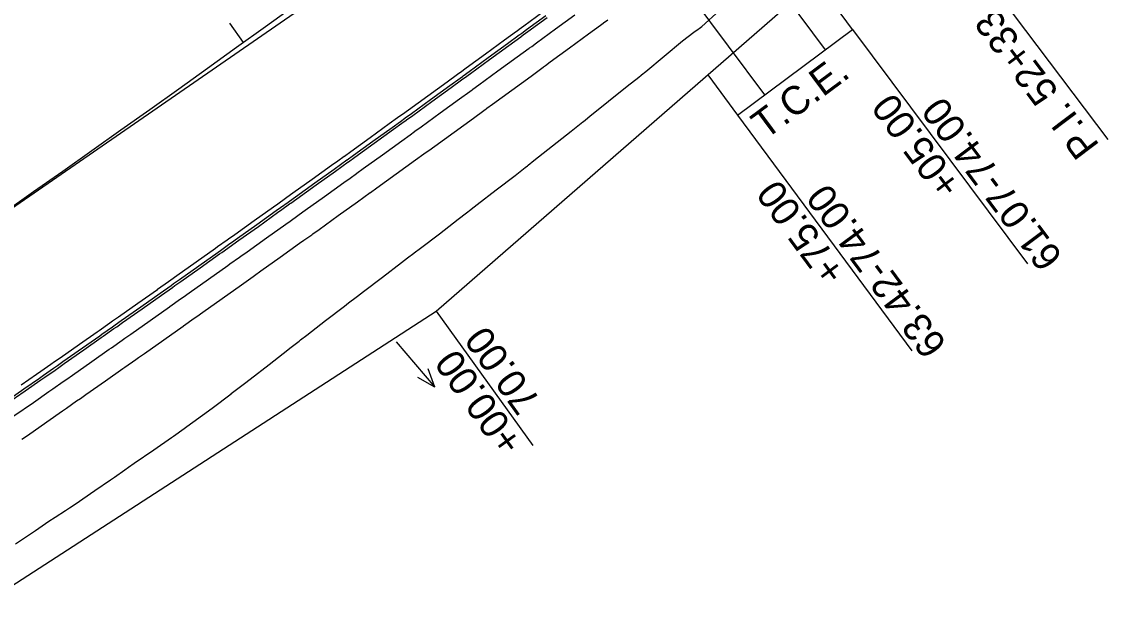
# Model space of a CAD drawing. Extents: x 1147550 to 1149124, y 2017436 to 2018779.
# Drawn here: x 1148333.9 to 1148565.1, y 2017968.7 to 2018092.6 of the extents above; entities that cross this region are included whole.
import ezdxf

# ---------------------------------------------------------------- set-up
doc = ezdxf.new("R2010")
doc.units = 0
for name, color, linetype in [('S_EDGE_CONCRETE', 7, 'Continuous'), ('S_ELECTRIC_UTILITIES', 7, 'Continuous'), ('S_HEADWALL', 7, 'Continuous'), ('S_IRON_PIN', 7, 'Continuous'), ('S_MAILBOX', 7, 'Continuous'), ('S_RDW_PT_SYM', 7, 'Continuous'), ('S_SECONDARY_CTL', 7, 'Continuous'), ('S_TANK', 7, 'Continuous'), ('S_TELEPHONE_UTILITIES', 7, 'Continuous')]:
    doc.layers.add(name, color=color, linetype=linetype)

msp = doc.modelspace()

# ---------------------------------------------------------------- linework, layer by layer
at = {"layer": 'S_EDGE_CONCRETE'}
msp.add_line((1148293.22, 2018026.54), (1148491.47, 2018163.46), dxfattribs=at)
msp.add_lwpolyline([(1148377.87, 2018092.3), (1148380.78, 2018088.23)], dxfattribs=at)
msp.add_arc((1145037.29, 2022741.09), 5729.58, 304.629463, 309.445337, dxfattribs=at)
at = {"layer": 'S_ELECTRIC_UTILITIES'}
for points in [[(1148509.76, 2018090.99), (1148546.79, 2018041.41)], [(1148485.37, 2018072.88), (1148522.25, 2018022.95)], [(1148421.63, 2018031.39), (1148442.06, 2018002.97)]]:
    msp.add_lwpolyline(points, dxfattribs=at)
at = {"layer": 'S_HEADWALL'}
for p, q in [((1148503.99, 2018086.7), (1148484.62, 2018112.78)), ((1148491.14, 2018077.16), (1148471.77, 2018103.24))]:
    msp.add_line(p, q, dxfattribs=at)
at = {"layer": 'S_IRON_PIN'}
for p, q in [((1148509.76, 2018090.99), (1148502.03, 2018101.35)), ((1148485.37, 2018072.88), (1148509.76, 2018090.99)), ((1148479.08, 2018081.39), (1148485.37, 2018072.88))]:
    msp.add_line(p, q, dxfattribs=at)
at = {"layer": 'S_MAILBOX'}
msp.add_lwpolyline([(1147623.68, 2017436.42), (1147751.67, 2017548.43), (1147958.55, 2017704.02), (1148020.45, 2017753.36), (1148124.6, 2017828.73), (1148174.25, 2017853.51), (1148282.74, 2017941.53), (1148421.63, 2018031.39), (1148612.18, 2018197.22), (1148639.91, 2018214.06), (1148753.45, 2018306.48), (1148799.03, 2018350.69)], dxfattribs=at)
at = {"layer": 'S_RDW_PT_SYM'}
msp.add_lwpolyline([(1148491.47, 2018163.46), (1148563.75, 2018067.67)], dxfattribs=at)
at = {"layer": 'S_SECONDARY_CTL'}
msp.add_lwpolyline([(1148332.6, 2017982.17), (1148336.8, 2017984.98), (1148339.66, 2017986.92), (1148340.99, 2017987.8), (1148343.17, 2017989.22), (1148344, 2017989.76), (1148345.22, 2017990.56), (1148349.41, 2017993.39), (1148352.7, 2017995.66), (1148353.56, 2017996.27), (1148355.73, 2017997.79), (1148356.51, 2017998.35), (1148357.69, 2017999.18), (1148361.84, 2018002.06), (1148365.59, 2018004.62), (1148366.01, 2018004.91), (1148368.31, 2018006.53), (1148368.88, 2018006.94), (1148370.12, 2018007.85), (1148374.19, 2018010.85), (1148378.21, 2018013.91), (1148378.23, 2018013.92), (1148380.5, 2018015.66), (1148381.02, 2018016.05), (1148382.23, 2018016.98), (1148386.24, 2018020.05), (1148390.23, 2018023.16), (1148390.67, 2018023.51), (1148392.64, 2018025.05), (1148392.93, 2018025.27), (1148394.21, 2018026.27), (1148398.19, 2018029.4), (1148402.2, 2018032.46), (1148403.09, 2018033.13), (1148404.71, 2018034.35), (1148404.96, 2018034.53), (1148406.24, 2018035.51), (1148410.25, 2018038.57), (1148414.26, 2018041.65), (1148415.56, 2018042.66), (1148416.89, 2018043.67), (1148416.93, 2018043.7), (1148418.28, 2018044.7), (1148422.31, 2018047.75), (1148426.3, 2018050.85), (1148428.03, 2018052.19), (1148428.92, 2018052.9), (1148429.02, 2018052.97), (1148430.29, 2018053.95), (1148434.3, 2018057.02), (1148438.3, 2018060.11), (1148440.45, 2018061.79), (1148440.94, 2018062.16), (1148441.08, 2018062.28), (1148442.29, 2018063.22), (1148446.26, 2018066.33), (1148450.22, 2018069.47), (1148452.67, 2018071.42), (1148452.78, 2018071.51), (1148453.21, 2018071.85), (1148454.17, 2018072.62), (1148458.11, 2018075.8), (1148462.03, 2018078.99), (1148464.49, 2018080.92), (1148465.02, 2018081.34), (1148465.08, 2018081.39), (1148466, 2018082.11), (1148469.9, 2018085.33), (1148473.78, 2018088.57), (1148476.12, 2018090.42), (1148477.04, 2018091.04), (1148477.25, 2018091.19), (1148477.83, 2018091.58), (1148481.57, 2018095.01)], dxfattribs=at)
at = {"layer": 'S_TANK'}
for p, q in [((1148413.18, 2018024.88), (1148421.33, 2018015.31)), ((1148421.33, 2018015.31), (1148419.9, 2018019.15)), ((1148421.33, 2018015.31), (1148417.77, 2018017.33))]:
    msp.add_line(p, q, dxfattribs=at)
at = {"layer": 'S_TELEPHONE_UTILITIES'}
for points in [[(1148333.8, 2018015.76), (1148337.06, 2018018.04), (1148337.93, 2018018.64), (1148340.09, 2018020.15), (1148340.87, 2018020.7), (1148342.05, 2018021.52), (1148346.16, 2018024.41), (1148349.86, 2018027), (1148350.28, 2018027.3), (1148352.56, 2018028.9), (1148353.14, 2018029.31), (1148354.39, 2018030.19), (1148358.5, 2018033.09), (1148362.61, 2018035.99), (1148362.63, 2018036), (1148364.95, 2018037.64), (1148365.48, 2018038.01), (1148366.71, 2018038.89), (1148370.81, 2018041.8), (1148374.91, 2018044.71), (1148375.37, 2018045.03), (1148377.4, 2018046.47), (1148377.69, 2018046.69), (1148379.01, 2018047.62), (1148383.11, 2018050.54), (1148387.2, 2018053.46), (1148388.09, 2018054.1), (1148389.74, 2018055.28), (1148389.99, 2018055.46), (1148391.29, 2018056.39), (1148395.37, 2018059.32), (1148399.46, 2018062.25), (1148400.79, 2018063.2), (1148402.14, 2018064.17), (1148402.18, 2018064.2), (1148403.54, 2018065.18), (1148407.62, 2018068.12), (1148411.7, 2018071.07), (1148413.46, 2018072.34), (1148414.38, 2018073), (1148414.48, 2018073.08), (1148415.77, 2018074.01), (1148419.84, 2018076.96), (1148423.91, 2018079.92), (1148426.11, 2018081.51), (1148426.6, 2018081.87), (1148426.75, 2018081.98), (1148427.98, 2018082.87), (1148432.04, 2018085.83), (1148436.1, 2018088.8), (1148438.62, 2018090.64), (1148438.73, 2018090.72), (1148439.17, 2018091.04), (1148440.16, 2018091.77), (1148444.22, 2018094.74)], [(1148330.25, 2018012.07), (1148334.38, 2018014.94), (1148337.64, 2018017.22), (1148338.5, 2018017.82), (1148340.66, 2018019.33), (1148341.44, 2018019.88), (1148342.62, 2018020.7), (1148346.74, 2018023.59), (1148350.43, 2018026.18), (1148350.85, 2018026.48), (1148353.14, 2018028.09), (1148353.71, 2018028.49), (1148354.97, 2018029.37), (1148359.08, 2018032.27), (1148363.18, 2018035.17), (1148363.2, 2018035.18), (1148365.52, 2018036.82), (1148366.05, 2018037.2), (1148367.29, 2018038.07), (1148371.39, 2018040.98), (1148375.49, 2018043.89), (1148375.95, 2018044.22), (1148377.98, 2018045.66), (1148378.27, 2018045.87), (1148379.59, 2018046.81), (1148383.69, 2018049.73), (1148387.78, 2018052.65), (1148388.67, 2018053.29), (1148390.32, 2018054.47), (1148390.57, 2018054.64), (1148391.87, 2018055.57), (1148395.96, 2018058.5), (1148400.04, 2018061.44), (1148401.37, 2018062.39), (1148402.72, 2018063.36), (1148402.76, 2018063.39), (1148404.12, 2018064.37), (1148408.2, 2018067.31), (1148412.28, 2018070.26), (1148414.05, 2018071.53), (1148414.96, 2018072.19), (1148415.06, 2018072.27), (1148416.36, 2018073.2), (1148420.43, 2018076.15), (1148424.5, 2018079.11), (1148426.69, 2018080.7), (1148427.19, 2018081.06), (1148427.34, 2018081.17), (1148428.57, 2018082.07), (1148432.63, 2018085.03), (1148436.69, 2018087.99), (1148439.21, 2018089.83), (1148439.32, 2018089.91), (1148439.76, 2018090.23), (1148440.75, 2018090.96), (1148444.81, 2018093.93)], [(1148330.54, 2018011.66), (1148334.66, 2018014.53), (1148337.92, 2018016.81), (1148338.79, 2018017.41), (1148340.95, 2018018.92), (1148341.73, 2018019.47), (1148342.91, 2018020.29), (1148347.02, 2018023.18), (1148350.72, 2018025.77), (1148351.14, 2018026.07), (1148353.43, 2018027.68), (1148354, 2018028.08), (1148355.25, 2018028.96), (1148359.37, 2018031.86), (1148363.47, 2018034.76), (1148363.49, 2018034.78), (1148365.81, 2018036.41), (1148366.34, 2018036.79), (1148367.58, 2018037.67), (1148371.68, 2018040.57), (1148375.78, 2018043.49), (1148376.24, 2018043.81), (1148378.27, 2018045.25), (1148378.56, 2018045.46), (1148379.88, 2018046.4), (1148383.98, 2018049.32), (1148388.07, 2018052.24), (1148388.96, 2018052.88), (1148390.61, 2018054.06), (1148390.86, 2018054.24), (1148392.16, 2018055.17), (1148396.25, 2018058.1), (1148400.33, 2018061.03), (1148401.66, 2018061.99), (1148403.01, 2018062.96), (1148403.05, 2018062.98), (1148404.42, 2018063.97), (1148408.5, 2018066.91), (1148412.57, 2018069.85), (1148414.34, 2018071.13), (1148415.26, 2018071.79), (1148415.36, 2018071.86), (1148416.65, 2018072.8), (1148420.72, 2018075.75), (1148424.79, 2018078.7), (1148426.99, 2018080.3), (1148427.48, 2018080.66), (1148427.63, 2018080.77), (1148428.86, 2018081.66), (1148432.92, 2018084.62), (1148436.99, 2018087.59), (1148439.5, 2018089.43), (1148439.61, 2018089.51), (1148440.05, 2018089.83), (1148441.05, 2018090.56), (1148445.1, 2018093.53)], [(1148332.25, 2018009.19), (1148336.38, 2018012.07), (1148339.64, 2018014.35), (1148340.5, 2018014.95), (1148342.67, 2018016.46), (1148343.45, 2018017.01), (1148344.63, 2018017.84), (1148348.75, 2018020.72), (1148352.44, 2018023.32), (1148352.87, 2018023.62), (1148355.15, 2018025.22), (1148355.73, 2018025.63), (1148356.98, 2018026.51), (1148361.09, 2018029.41), (1148365.2, 2018032.31), (1148365.22, 2018032.33), (1148367.54, 2018033.97), (1148368.07, 2018034.34), (1148369.31, 2018035.22), (1148373.42, 2018038.13), (1148377.52, 2018041.04), (1148377.98, 2018041.37), (1148380.01, 2018042.81), (1148380.3, 2018043.02), (1148381.62, 2018043.96), (1148385.72, 2018046.88), (1148389.81, 2018049.8), (1148390.71, 2018050.44), (1148392.36, 2018051.62), (1148392.61, 2018051.8), (1148393.91, 2018052.73), (1148398, 2018055.66), (1148402.08, 2018058.59), (1148403.42, 2018059.55), (1148404.76, 2018060.52), (1148404.8, 2018060.55), (1148406.17, 2018061.53), (1148410.25, 2018064.47), (1148414.33, 2018067.42), (1148416.1, 2018068.69), (1148417.01, 2018069.36), (1148417.11, 2018069.43), (1148418.41, 2018070.37), (1148422.48, 2018073.32), (1148426.56, 2018076.28), (1148428.75, 2018077.87), (1148429.25, 2018078.23), (1148429.39, 2018078.34), (1148430.63, 2018079.24), (1148434.69, 2018082.2), (1148438.76, 2018085.17), (1148441.27, 2018087.01), (1148441.38, 2018087.09), (1148441.83, 2018087.41), (1148442.82, 2018088.14), (1148446.88, 2018091.11), (1148450.93, 2018094.09)], [(1148333.91, 2018004.26), (1148335.11, 2018005.09), (1148339.24, 2018007.97), (1148342.5, 2018010.25), (1148343.37, 2018010.85), (1148345.53, 2018012.37), (1148346.32, 2018012.91), (1148347.5, 2018013.74), (1148351.62, 2018016.63), (1148355.32, 2018019.23), (1148355.74, 2018019.52), (1148358.03, 2018021.13), (1148358.61, 2018021.54), (1148359.86, 2018022.42), (1148363.98, 2018025.32), (1148368.09, 2018028.23), (1148368.11, 2018028.24), (1148370.43, 2018029.88), (1148370.96, 2018030.26), (1148372.2, 2018031.14), (1148376.31, 2018034.05), (1148380.42, 2018036.96), (1148380.88, 2018037.29), (1148382.91, 2018038.73), (1148383.2, 2018038.94), (1148384.52, 2018039.88), (1148388.62, 2018042.81), (1148392.72, 2018045.73), (1148393.62, 2018046.37), (1148395.27, 2018047.55), (1148395.51, 2018047.73), (1148396.82, 2018048.66), (1148400.91, 2018051.6), (1148405, 2018054.53), (1148406.33, 2018055.49), (1148407.68, 2018056.46), (1148407.72, 2018056.49), (1148409.09, 2018057.47), (1148413.18, 2018060.42), (1148417.26, 2018063.37), (1148419.03, 2018064.64), (1148419.95, 2018065.31), (1148420.04, 2018065.38), (1148421.34, 2018066.32), (1148425.42, 2018069.27), (1148429.49, 2018072.23), (1148431.69, 2018073.83), (1148432.19, 2018074.19), (1148432.34, 2018074.3), (1148433.57, 2018075.19), (1148437.64, 2018078.16), (1148441.71, 2018081.13), (1148444.23, 2018082.97), (1148444.34, 2018083.05), (1148444.78, 2018083.37), (1148445.77, 2018084.1), (1148449.83, 2018087.08), (1148453.89, 2018090.06), (1148456.42, 2018091.91), (1148456.95, 2018092.31), (1148457.02, 2018092.35), (1148457.95, 2018093.04)]]:
    msp.add_lwpolyline(points, dxfattribs=at)

# ---------------------------------------------------------------- texts
at = {"layer": 'S_ELECTRIC_UTILITIES'}
for s, rotation, p in [('+05.00', 126.7506, (1148533.07, 2018058.12)), ('61.07-74.00', 126.7506, (1148554.44, 2018042.87)), ('+75.00', 126.4506, (1148508.61, 2018039.72)), ('63.42-74.00', 126.4506, (1148529.9, 2018024.36)), ('70.00', 125.7006, (1148443.9, 2018012.4)), ('+00.00', 125.7006, (1148440.32, 2018003.68))]:
    msp.add_text(s, height=6, rotation=rotation, dxfattribs=at).set_placement(p)
at = {"layer": 'S_IRON_PIN'}
msp.add_text('T.C.E.', height=6, rotation=36.6006, dxfattribs=at).set_placement((1148491.28, 2018067.55))
at = {"layer": 'S_RDW_PT_SYM'}
msp.add_text('P.I. 52+33.82', height=6, rotation=127.0374, dxfattribs=at).set_placement((1148562.15, 2018066.47))

doc.saveas('drawing.dxf')
